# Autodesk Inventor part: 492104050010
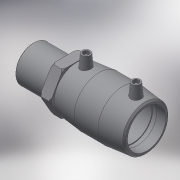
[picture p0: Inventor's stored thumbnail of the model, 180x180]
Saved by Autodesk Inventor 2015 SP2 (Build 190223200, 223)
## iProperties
Created: 2017-06
Part Number: 492104050010
Material: Generic
Description: PLASSON Male Transition Coupler 50 x 1"
Document SubType Name: Modeling
Designer: KIM
Mass: 207.606 g
Surface Area: 534.142 cm^2
Volume: 207.606 cm^3
Density: 1 g/cm^3
Appearance: Default
Author: KIM
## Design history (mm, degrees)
derived "492104.ipt"
feature "Solid1::492104.ipt"
tag "TaggingFeature1"
body "Solid1"
other parameters: "d0" = 101, "d2" = 67, "d3" = 49, "d4" = 33.66667, "d5" = 60.3, "d6" = 47.5, "d8" = 168 deg, "d10" = 19.6, "d11" = 6.53333, "d29" = 51, "d30" = 14, "d31" = 35.35, "d34" = 5 deg, "d41" = 4, "d42" = 14, "d43" = 0, "d48" = 3, "d49" = 0, "d57" = 38, "d58" = 33.249, "d59" = 26.5992, "d60" = 30.6, "d61" = 67, "d62" = 0.66498, "d65" = 2.01, "d70" = 0.1, "d71" = 34, "d72" = 8.5, "d73" = 19.6, "d75" = 0, "L_" = 135, "L_1" = 49, "D_1" = 67, "A_" = 51, "d_2" = 12, "L_2" = 34, "D_" = 38, "R_" = 33.249
